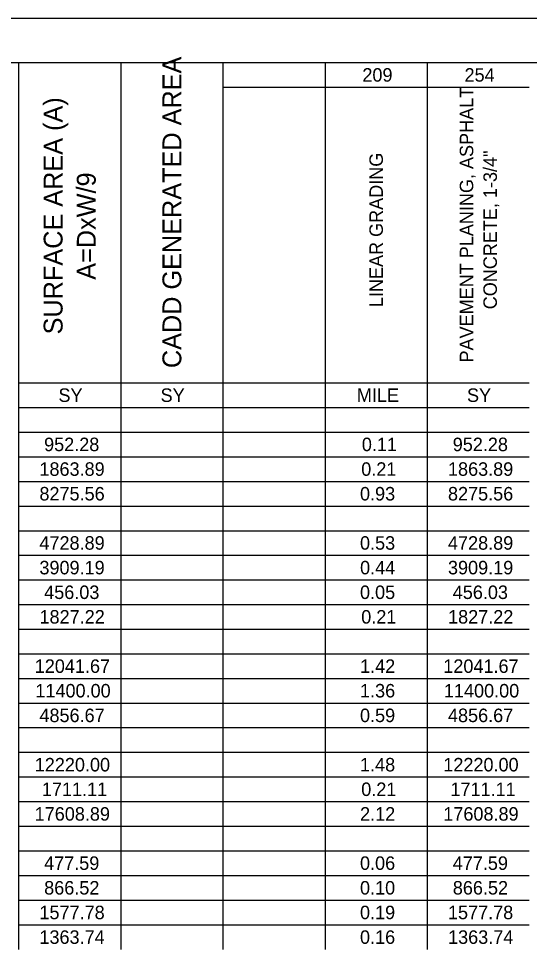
# Model space of a CAD drawing. Extents: x 0 to 34.4, y 0 to 47.
# Drawn here: x 10.58 to 16.38, y 11.43 to 22 of the extents above; entities that cross this region are included whole.
import ezdxf

# ---------------------------------------------------------------- set-up
doc = ezdxf.new("R2010")
doc.units = 0
for name, color, linetype in [('SH_Border', 7, 'Continuous'), ('SH_Cut_Line', 7, 'Continuous'), ('SH_Text', 7, 'Continuous')]:
    doc.layers.add(name, color=color, linetype=linetype)

msp = doc.modelspace()

# ---------------------------------------------------------------- linework, layer by layer
at = {"layer": 'SH_Border'}
msp.add_lwpolyline([(1.5, 21.5), (33.5, 21.5), (33.5, 0.5), (1.5, 0.5)], close=True, dxfattribs=at)
at = {"layer": 'SH_Cut_Line'}
msp.add_lwpolyline([(0, 0), (34, 0), (34, 22), (0, 22)], close=True, dxfattribs=at)
at = {"layer": 'SH_Text'}
for p, q in [((10.584, 21.5), (11.743, 21.5)), ((10.584, 21.5), (10.584, 21.22)), ((11.743, 21.5), (14.061, 21.5)), ((11.743, 21.5), (11.743, 21.22)), ((12.902, 21.5), (12.902, 21.22)), ((14.061, 21.5), (15.22, 21.5)), ((14.061, 21.5), (14.061, 21.22)), ((15.22, 21.5), (16.378, 21.5)), ((15.22, 21.5), (15.22, 21.22)), ((10.584, 21.22), (10.584, 20.941)), ((11.743, 21.22), (11.743, 20.941)), ((12.902, 21.22), (14.061, 21.22)), ((12.902, 21.22), (12.902, 20.941)), ((14.061, 21.22), (15.22, 21.22)), ((14.061, 21.22), (14.061, 20.941)), ((15.22, 21.22), (16.378, 21.22)), ((15.22, 21.22), (15.22, 20.941)), ((10.584, 20.941), (10.584, 20.661)), ((11.743, 20.941), (11.743, 20.661)), ((12.902, 20.941), (12.902, 20.661)), ((14.061, 20.941), (14.061, 20.661)), ((15.22, 20.941), (15.22, 20.661)), ((10.584, 20.661), (10.584, 20.101)), ((11.743, 20.661), (11.743, 20.101)), ((12.902, 20.661), (12.902, 20.101)), ((14.061, 20.661), (14.061, 20.101)), ((15.22, 20.661), (15.22, 20.101)), ((10.584, 20.101), (10.584, 19.822)), ((11.743, 20.101), (11.743, 19.822)), ((12.902, 20.101), (12.902, 19.822)), ((14.061, 20.101), (14.061, 19.822)), ((15.22, 20.101), (15.22, 19.822)), ((10.584, 19.822), (10.584, 19.542)), ((11.743, 19.822), (11.743, 19.542)), ((12.902, 19.822), (12.902, 19.542)), ((14.061, 19.822), (14.061, 19.542)), ((15.22, 19.822), (15.22, 19.542)), ((10.584, 19.542), (10.584, 19.262)), ((11.743, 19.542), (11.743, 19.262)), ((12.902, 19.542), (12.902, 19.262)), ((14.061, 19.542), (14.061, 19.262)), ((15.22, 19.542), (15.22, 19.262)), ((10.584, 19.262), (10.584, 18.983)), ((11.743, 19.262), (11.743, 18.983)), ((12.902, 19.262), (12.902, 18.983)), ((14.061, 19.262), (14.061, 18.983)), ((15.22, 19.262), (15.22, 18.983)), ((10.584, 18.983), (10.584, 18.703)), ((11.743, 18.983), (11.743, 18.703)), ((12.902, 18.983), (12.902, 18.703)), ((14.061, 18.983), (14.061, 18.703)), ((15.22, 18.983), (15.22, 18.703)), ((10.584, 18.703), (10.584, 18.423)), ((11.743, 18.703), (11.743, 18.423)), ((12.902, 18.703), (12.902, 18.423)), ((14.061, 18.703), (14.061, 18.423)), ((15.22, 18.703), (15.22, 18.423)), ((10.584, 18.423), (10.584, 18.143)), ((11.743, 18.423), (11.743, 18.143)), ((12.902, 18.423), (12.902, 18.143)), ((14.061, 18.423), (14.061, 18.143)), ((15.22, 18.423), (15.22, 18.143)), ((10.584, 18.143), (10.584, 17.864)), ((11.743, 18.143), (11.743, 17.864)), ((12.902, 18.143), (12.902, 17.864)), ((14.061, 18.143), (14.061, 17.864)), ((15.22, 18.143), (15.22, 17.864)), ((10.584, 17.864), (11.743, 17.864)), ((10.584, 17.864), (10.584, 17.584)), ((11.743, 17.864), (14.061, 17.864)), ((11.743, 17.864), (11.743, 17.584)), ((12.902, 17.864), (12.902, 17.584)), ((14.061, 17.864), (15.22, 17.864)), ((14.061, 17.864), (14.061, 17.584)), ((15.22, 17.864), (16.378, 17.864)), ((15.22, 17.864), (15.22, 17.584)), ((10.584, 17.584), (11.743, 17.584)), ((10.584, 17.584), (10.584, 17.304)), ((11.743, 17.584), (14.061, 17.584)), ((11.743, 17.584), (11.743, 17.304)), ((12.902, 17.584), (12.902, 17.304)), ((14.061, 17.584), (15.22, 17.584)), ((14.061, 17.584), (14.061, 17.304)), ((15.22, 17.584), (16.378, 17.584)), ((15.22, 17.584), (15.22, 17.304)), ((10.584, 17.304), (11.743, 17.304)), ((10.584, 17.304), (10.584, 17.024)), ((11.743, 17.304), (14.061, 17.304)), ((11.743, 17.304), (11.743, 17.024)), ((12.902, 17.304), (12.902, 17.024)), ((14.061, 17.304), (15.22, 17.304)), ((14.061, 17.304), (14.061, 17.024)), ((15.22, 17.304), (16.378, 17.304)), ((15.22, 17.304), (15.22, 17.024)), ((10.584, 17.024), (11.743, 17.024)), ((10.584, 17.024), (10.584, 16.745)), ((11.743, 17.024), (14.061, 17.024)), ((11.743, 17.024), (11.743, 16.745)), ((12.902, 17.024), (12.902, 16.745)), ((14.061, 17.024), (15.22, 17.024)), ((14.061, 17.024), (14.061, 16.745)), ((15.22, 17.024), (16.378, 17.024)), ((15.22, 17.024), (15.22, 16.745)), ((10.584, 16.745), (11.743, 16.745)), ((10.584, 16.745), (10.584, 16.185)), ((11.743, 16.745), (14.061, 16.745)), ((11.743, 16.745), (11.743, 16.185)), ((12.902, 16.745), (12.902, 16.185)), ((14.061, 16.745), (15.22, 16.745)), ((14.061, 16.745), (14.061, 16.185)), ((15.22, 16.745), (16.378, 16.745)), ((15.22, 16.745), (15.22, 16.185)), ((10.584, 16.465), (11.743, 16.465)), ((11.743, 16.465), (14.061, 16.465)), ((14.061, 16.465), (15.22, 16.465)), ((15.22, 16.465), (16.378, 16.465)), ((10.584, 16.185), (11.743, 16.185)), ((10.584, 16.185), (10.584, 15.906)), ((11.743, 16.185), (14.061, 16.185)), ((11.743, 16.185), (11.743, 15.906)), ((12.902, 16.185), (12.902, 15.906)), ((14.061, 16.185), (15.22, 16.185)), ((14.061, 16.185), (14.061, 15.906)), ((15.22, 16.185), (16.378, 16.185)), ((15.22, 16.185), (15.22, 15.906)), ((10.584, 15.906), (11.743, 15.906)), ((10.584, 15.906), (10.584, 15.626)), ((11.743, 15.906), (14.061, 15.906)), ((11.743, 15.906), (11.743, 15.626)), ((12.902, 15.906), (12.902, 15.626)), ((14.061, 15.906), (15.22, 15.906)), ((14.061, 15.906), (14.061, 15.626)), ((15.22, 15.906), (16.378, 15.906)), ((15.22, 15.906), (15.22, 15.626)), ((10.584, 15.626), (11.743, 15.626)), ((10.584, 15.626), (10.584, 15.346)), ((11.743, 15.626), (14.061, 15.626)), ((11.743, 15.626), (11.743, 15.346)), ((12.902, 15.626), (12.902, 15.346)), ((14.061, 15.626), (15.22, 15.626)), ((14.061, 15.626), (14.061, 15.346)), ((15.22, 15.626), (16.378, 15.626)), ((15.22, 15.626), (15.22, 15.346)), ((10.584, 15.346), (11.743, 15.346)), ((10.584, 15.346), (10.584, 14.787)), ((11.743, 15.346), (14.061, 15.346)), ((11.743, 15.346), (11.743, 14.787)), ((12.902, 15.346), (12.902, 14.787)), ((14.061, 15.346), (15.22, 15.346)), ((14.061, 15.346), (14.061, 14.787)), ((15.22, 15.346), (16.378, 15.346)), ((15.22, 15.346), (15.22, 14.787)), ((10.584, 15.066), (11.743, 15.066)), ((11.743, 15.066), (14.061, 15.066)), ((14.061, 15.066), (15.22, 15.066)), ((15.22, 15.066), (16.378, 15.066)), ((10.584, 14.787), (11.743, 14.787)), ((10.584, 14.787), (10.584, 14.507)), ((11.743, 14.787), (14.061, 14.787)), ((11.743, 14.787), (11.743, 14.507)), ((12.902, 14.787), (12.902, 14.507)), ((14.061, 14.787), (15.22, 14.787)), ((14.061, 14.787), (14.061, 14.507)), ((15.22, 14.787), (16.378, 14.787)), ((15.22, 14.787), (15.22, 14.507)), ((10.584, 14.507), (11.743, 14.507)), ((10.584, 14.507), (10.584, 14.227)), ((11.743, 14.507), (14.061, 14.507)), ((11.743, 14.507), (11.743, 14.227)), ((12.902, 14.507), (12.902, 14.227)), ((14.061, 14.507), (15.22, 14.507)), ((14.061, 14.507), (14.061, 14.227)), ((15.22, 14.507), (16.378, 14.507)), ((15.22, 14.507), (15.22, 14.227)), ((10.584, 14.227), (11.743, 14.227)), ((10.584, 14.227), (10.584, 13.948)), ((11.743, 14.227), (14.061, 14.227)), ((11.743, 14.227), (11.743, 13.948)), ((12.902, 14.227), (12.902, 13.948)), ((14.061, 14.227), (15.22, 14.227)), ((14.061, 14.227), (14.061, 13.948)), ((15.22, 14.227), (16.378, 14.227)), ((15.22, 14.227), (15.22, 13.948)), ((10.584, 13.948), (11.743, 13.948)), ((10.584, 13.948), (10.584, 13.108)), ((11.743, 13.948), (14.061, 13.948)), ((11.743, 13.948), (11.743, 13.108)), ((12.902, 13.948), (12.902, 13.108)), ((14.061, 13.948), (15.22, 13.948)), ((14.061, 13.948), (14.061, 13.108)), ((15.22, 13.948), (16.378, 13.948)), ((15.22, 13.948), (15.22, 13.108)), ((10.584, 13.668), (11.743, 13.668)), ((11.743, 13.668), (14.061, 13.668)), ((14.061, 13.668), (15.22, 13.668)), ((15.22, 13.668), (16.378, 13.668)), ((10.584, 13.388), (11.743, 13.388)), ((11.743, 13.388), (14.061, 13.388)), ((14.061, 13.388), (15.22, 13.388)), ((15.22, 13.388), (16.378, 13.388)), ((10.584, 13.108), (11.743, 13.108)), ((10.584, 13.108), (10.584, 12.829)), ((11.743, 13.108), (14.061, 13.108)), ((11.743, 13.108), (11.743, 12.829)), ((12.902, 13.108), (12.902, 12.829)), ((14.061, 13.108), (15.22, 13.108)), ((14.061, 13.108), (14.061, 12.829)), ((15.22, 13.108), (16.378, 13.108)), ((15.22, 13.108), (15.22, 12.829)), ((10.584, 12.829), (11.743, 12.829)), ((10.584, 12.829), (10.584, 11.71)), ((11.743, 12.829), (14.061, 12.829)), ((11.743, 12.829), (11.743, 11.71)), ((12.902, 12.829), (12.902, 11.71)), ((14.061, 12.829), (15.22, 12.829)), ((14.061, 12.829), (14.061, 11.71)), ((15.22, 12.829), (16.378, 12.829)), ((15.22, 12.829), (15.22, 11.71)), ((10.584, 12.549), (11.743, 12.549)), ((11.743, 12.549), (14.061, 12.549)), ((14.061, 12.549), (15.22, 12.549)), ((15.22, 12.549), (16.378, 12.549)), ((10.584, 12.269), (11.743, 12.269)), ((11.743, 12.269), (14.061, 12.269)), ((14.061, 12.269), (15.22, 12.269)), ((15.22, 12.269), (16.378, 12.269)), ((10.584, 11.99), (11.743, 11.99)), ((11.743, 11.99), (14.061, 11.99)), ((14.061, 11.99), (15.22, 11.99)), ((15.22, 11.99), (16.378, 11.99)), ((10.584, 11.71), (11.743, 11.71)), ((10.584, 11.71), (10.584, 11.43)), ((11.743, 11.71), (14.061, 11.71)), ((11.743, 11.71), (11.743, 11.43)), ((12.902, 11.71), (12.902, 11.43)), ((14.061, 11.71), (15.22, 11.71)), ((14.061, 11.71), (14.061, 11.43)), ((15.22, 11.71), (16.378, 11.71)), ((15.22, 11.71), (15.22, 11.43))]:
    msp.add_line(p, q, dxfattribs=at)

# ---------------------------------------------------------------- texts
for s, height, p in [('CADD GENERATED AREA', 0.21445, (12.43, 18.031)), ('PAVEMENT PLANING, ASPHALT ', 0.15318, (15.742, 18.095)), ('SURFACE AREA (A) ', 0.21445, (11.083, 18.414)), ('LINEAR GRADING', 0.15318, (14.717, 18.724)), ('CONCRETE, 1-3/4"', 0.15318, (16.01, 18.699)), ('A=DxW/9', 0.2145, (11.459, 19.034))]:
    msp.add_text(s, height=height, rotation=90, dxfattribs=at).set_placement(p)
for s, p in [('209', (14.484, 21.284)), ('254', (15.643, 21.284)), ('SY', (11.036, 17.647)), ('SY', (12.195, 17.647)), ('MILE', (14.421, 17.647)), ('SY', (15.671, 17.647)), ('952.28', (10.873, 17.088)), ('0.11', (14.478, 17.088)), ('952.28', (15.509, 17.088)), ('1863.89', (10.82, 16.808)), ('0.21', (14.471, 16.808)), ('1863.89', (15.455, 16.808)), ('8275.56', (10.82, 16.528)), ('0.93', (14.457, 16.528)), ('8275.56', (15.455, 16.528)), ('4728.89', (10.82, 15.969)), ('0.53', (14.457, 15.969)), ('4728.89', (15.455, 15.969)), ('3909.19', (10.82, 15.689)), ('0.44', (14.458, 15.689)), ('3909.19', (15.455, 15.689)), ('456.03', (10.874, 15.409)), ('0.05', (14.457, 15.409)), ('456.03', (15.509, 15.409)), ('1827.22', (10.821, 15.13)), ('0.21', (14.471, 15.13)), ('1827.22', (15.456, 15.13)), ('12041.67', (10.767, 14.57)), ('1.42', (14.458, 14.57)), ('12041.67', (15.402, 14.57)), ('11400.00', (10.774, 14.291)), ('1.36', (14.457, 14.291)), ('11400.00', (15.409, 14.291)), ('4856.67', (10.82, 14.011)), ('0.59', (14.457, 14.011)), ('4856.67', (15.455, 14.011)), ('12220.00', (10.767, 13.451)), ('1.48', (14.457, 13.451)), ('12220.00', (15.402, 13.451)), ('1711.11', (10.848, 13.172)), ('0.21', (14.471, 13.172)), ('1711.11', (15.483, 13.172)), ('17608.89', (10.766, 12.892)), ('2.12', (14.458, 12.892)), ('17608.89', (15.402, 12.892)), ('477.59', (10.873, 12.333)), ('0.06', (14.457, 12.333)), ('477.59', (15.509, 12.333)), ('866.52', (10.874, 12.053)), ('0.10', (14.457, 12.053)), ('866.52', (15.51, 12.053)), ('1577.78', (10.82, 11.773)), ('0.19', (14.457, 11.773)), ('1577.78', (15.455, 11.773)), ('1363.74', (10.82, 11.493)), ('0.16', (14.457, 11.493)), ('1363.74', (15.456, 11.493))]:
    msp.add_text(s, height=0.1532, dxfattribs=at).set_placement(p)

doc.saveas('drawing.dxf')
